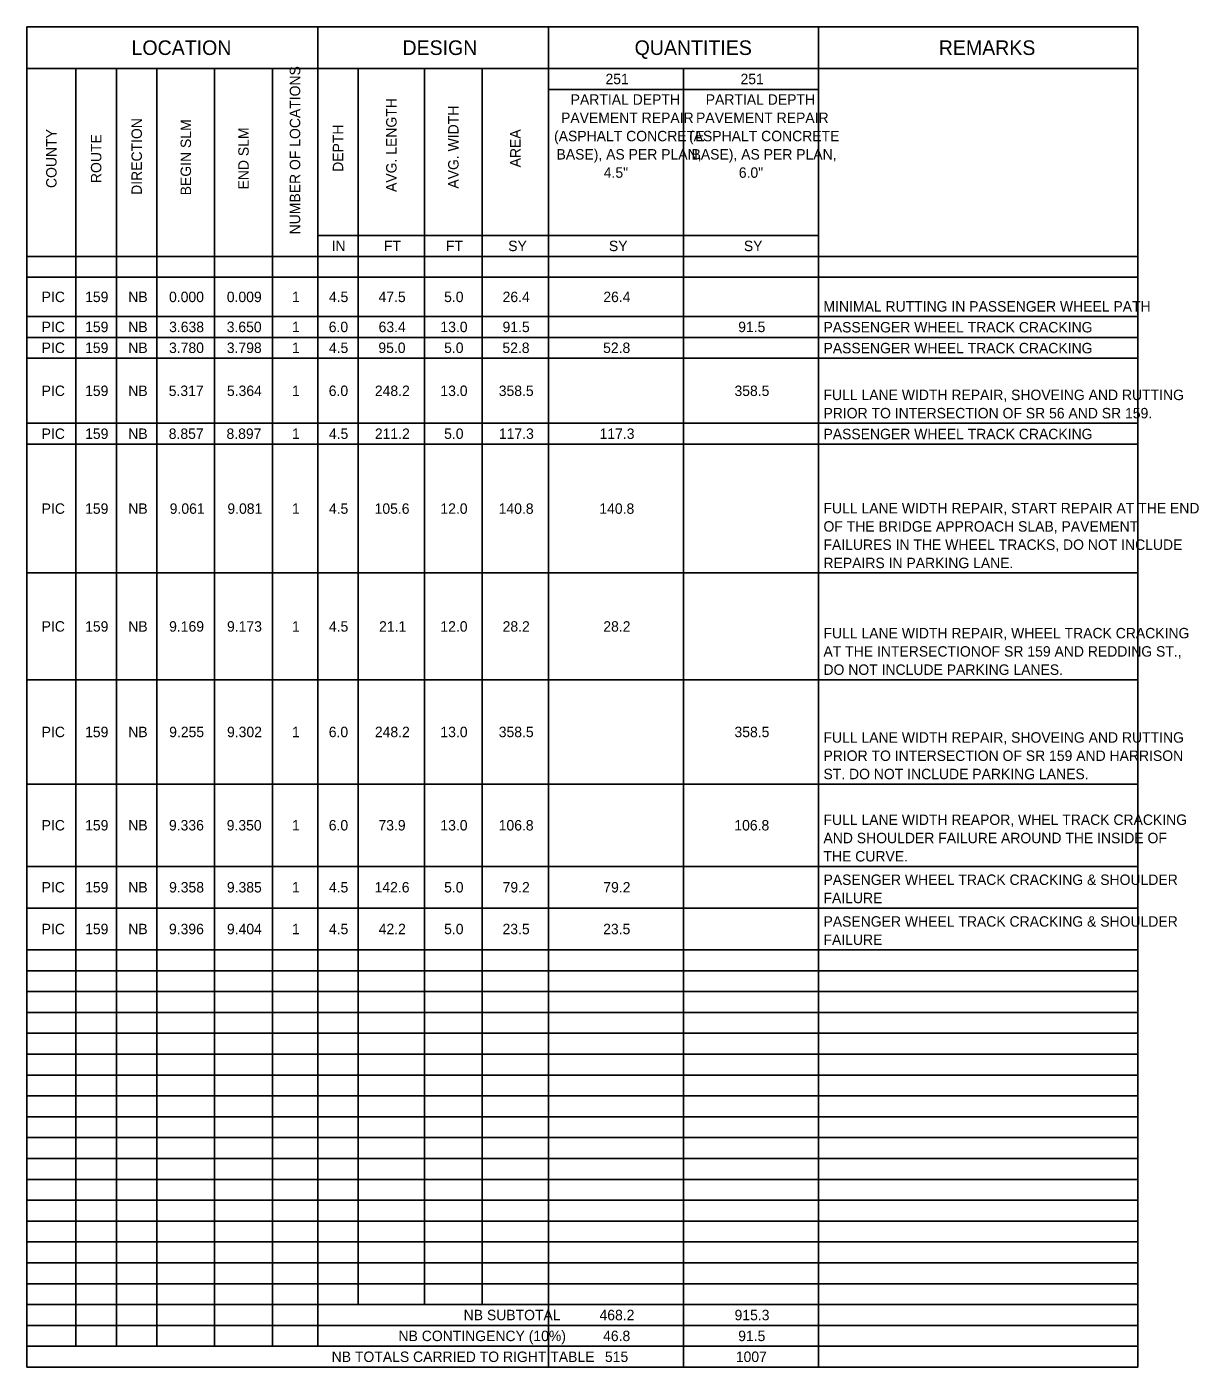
# Model space of a CAD drawing. Extents: x 0 to 66.4, y 0 to 22.
# Drawn here: x 35.12 to 50.75, y 3.76 to 21.75 of the extents above; entities that cross this region are included whole.
import ezdxf

# ---------------------------------------------------------------- set-up
doc = ezdxf.new("R2010")
doc.units = 0
doc.layers.add('Default', color=7, linetype='Continuous')

msp = doc.modelspace()

# ---------------------------------------------------------------- linework, layer by layer
at = {"layer": 'Default'}
for p, q in [((35.118, 21.75), (50.023, 21.75)), ((35.118, 21.75), (35.118, 3.764)), ((39.021, 21.75), (39.021, 4.044)), ((42.118, 21.75), (42.118, 3.764)), ((45.741, 21.75), (45.741, 3.764)), ((50.023, 21.75), (50.023, 3.764)), ((35.118, 21.19), (50.023, 21.19)), ((35.776, 21.19), (35.776, 4.044)), ((36.32, 21.19), (36.32, 4.044)), ((36.863, 21.19), (36.863, 4.044)), ((37.638, 21.19), (37.638, 4.044)), ((38.412, 21.19), (38.412, 4.044)), ((39.565, 21.19), (39.565, 4.604)), ((40.454, 21.19), (40.454, 4.604)), ((41.228, 21.19), (41.228, 4.604)), ((43.929, 21.19), (43.929, 3.764)), ((42.118, 20.91), (45.741, 20.91)), ((39.021, 18.95), (45.741, 18.95)), ((35.118, 18.67), (50.023, 18.67)), ((35.118, 18.39), (50.023, 18.39)), ((35.118, 17.863), (50.023, 17.863)), ((35.118, 17.583), (50.023, 17.583)), ((35.118, 17.303), (50.023, 17.303)), ((35.118, 16.43), (50.023, 16.43)), ((35.118, 16.15), (50.023, 16.15)), ((35.118, 14.421), (50.023, 14.421)), ((35.118, 12.988), (50.023, 12.988)), ((35.118, 11.588), (50.023, 11.588)), ((35.118, 10.484), (50.023, 10.484)), ((35.118, 9.924), (50.023, 9.924)), ((35.118, 9.364), (50.023, 9.364)), ((35.118, 9.084), (50.023, 9.084)), ((35.118, 8.804), (50.023, 8.804)), ((35.118, 8.524), (50.023, 8.524)), ((35.118, 8.244), (50.023, 8.244)), ((35.118, 7.964), (50.023, 7.964)), ((35.118, 7.684), (50.023, 7.684)), ((35.118, 7.404), (50.023, 7.404)), ((35.118, 7.124), (50.023, 7.124)), ((35.118, 6.844), (50.023, 6.844)), ((35.118, 6.564), (50.023, 6.564)), ((35.118, 6.284), (50.023, 6.284)), ((35.118, 6.004), (50.023, 6.004)), ((35.118, 5.724), (50.023, 5.724)), ((35.118, 5.444), (50.023, 5.444)), ((35.118, 5.164), (50.023, 5.164)), ((35.118, 4.884), (50.023, 4.884)), ((35.118, 4.604), (50.023, 4.604)), ((35.118, 4.324), (50.023, 4.324)), ((35.118, 4.044), (50.023, 4.044)), ((35.118, 3.764), (50.023, 3.764))]:
    msp.add_line(p, q, dxfattribs=at)

# ---------------------------------------------------------------- texts
for s, height, p in [('LOCATION', 0.196, (36.523, 21.372)), ('DESIGN', 0.196, (40.158, 21.372)), ('QUANTITIES', 0.196, (43.273, 21.372)), ('REMARKS', 0.196, (47.354, 21.372)), ('251', 0.14, (42.882, 20.98)), ('251', 0.14, (44.694, 20.98)), ('PARTIAL DEPTH ', 0.14, (42.415, 20.704)), ('PARTIAL DEPTH ', 0.14, (44.227, 20.704)), ('PAVEMENT REPAIR ', 0.14, (42.286, 20.459)), ('PAVEMENT REPAIR ', 0.14, (44.097, 20.459)), ('(ASPHALT CONCRETE ', 0.14, (42.192, 20.214)), ('(ASPHALT CONCRETE ', 0.14, (44.003, 20.214)), ('BASE), AS PER PLAN, ', 0.14, (42.225, 19.969)), ('BASE), AS PER PLAN, ', 0.14, (44.037, 19.969)), ('4.5"', 0.14, (42.859, 19.724)), ('6.0"', 0.14, (44.671, 19.724)), ('IN', 0.14, (39.207, 18.74)), ('FT', 0.14, (39.909, 18.74)), ('FT', 0.14, (40.741, 18.74)), ('SY', 0.14, (41.577, 18.74)), ('SY', 0.14, (42.928, 18.74)), ('SY', 0.14, (44.739, 18.74)), ('PIC', 0.14, (35.317, 18.056)), ('159', 0.14, (35.9, 18.056)), ('NB', 0.14, (36.479, 18.056)), ('0.000', 0.14, (37.026, 18.056)), ('0.009', 0.14, (37.801, 18.056)), ('1', 0.14, (38.676, 18.056)), ('4.5', 0.14, (39.171, 18.056)), ('47.5', 0.14, (39.837, 18.056)), ('5.0', 0.14, (40.717, 18.056)), ('26.4', 0.14, (41.502, 18.056)), ('26.4', 0.14, (42.853, 18.056)), ('MINIMAL RUTTING IN PASSENGER WHEEL PATH', 0.14, (45.807, 17.929)), ('PIC', 0.14, (35.317, 17.653)), ('159', 0.14, (35.9, 17.653)), ('NB', 0.14, (36.479, 17.653)), ('3.638', 0.14, (37.027, 17.653)), ('3.650', 0.14, (37.8, 17.653)), ('1', 0.14, (38.676, 17.653)), ('6.0', 0.14, (39.169, 17.653)), ('63.4', 0.14, (39.838, 17.653)), ('13.0', 0.14, (40.667, 17.653)), ('91.5', 0.14, (41.501, 17.653)), ('91.5', 0.14, (44.663, 17.653)), ('PASSENGER WHEEL TRACK CRACKING', 0.14, (45.807, 17.649)), ('PIC', 0.14, (35.317, 17.373)), ('159', 0.14, (35.9, 17.373)), ('NB', 0.14, (36.479, 17.373)), ('3.780', 0.14, (37.026, 17.373)), ('3.798', 0.14, (37.801, 17.373)), ('1', 0.14, (38.676, 17.373)), ('4.5', 0.14, (39.171, 17.373)), ('95.0', 0.14, (39.835, 17.373)), ('5.0', 0.14, (40.717, 17.373)), ('52.8', 0.14, (41.499, 17.373)), ('52.8', 0.14, (42.85, 17.373)), ('PASSENGER WHEEL TRACK CRACKING', 0.14, (45.807, 17.369)), ('PIC', 0.14, (35.317, 16.796)), ('159', 0.14, (35.9, 16.796)), ('NB', 0.14, (36.479, 16.796)), ('5.317', 0.14, (37.022, 16.796)), ('5.364', 0.14, (37.803, 16.796)), ('1', 0.14, (38.676, 16.796)), ('6.0', 0.14, (39.169, 16.796)), ('248.2', 0.14, (39.788, 16.796)), ('13.0', 0.14, (40.667, 16.796)), ('358.5', 0.14, (41.45, 16.796)), ('358.5', 0.14, (44.613, 16.796)), ('FULL LANE WIDTH REPAIR, SHOVEING AND RUTTING ', 0.14, (45.807, 16.741)), ('PRIOR TO INTERSECTION OF SR 56 AND SR 159.', 0.14, (45.807, 16.496)), ('PIC', 0.14, (35.317, 16.22)), ('159', 0.14, (35.9, 16.22)), ('NB', 0.14, (36.479, 16.22)), ('8.857', 0.14, (37.022, 16.22)), ('8.897', 0.14, (37.797, 16.22)), ('1', 0.14, (38.676, 16.22)), ('4.5', 0.14, (39.171, 16.22)), ('211.2', 0.14, (39.788, 16.22)), ('5.0', 0.14, (40.717, 16.22)), ('117.3', 0.14, (41.452, 16.22)), ('117.3', 0.14, (42.803, 16.22)), ('PASSENGER WHEEL TRACK CRACKING', 0.14, (45.807, 16.216)), ('PIC', 0.14, (35.317, 15.215)), ('159', 0.14, (35.9, 15.215)), ('NB', 0.14, (36.479, 15.215)), ('9.061', 0.14, (37.035, 15.215)), ('9.081', 0.14, (37.809, 15.215)), ('1', 0.14, (38.676, 15.215)), ('4.5', 0.14, (39.171, 15.215)), ('105.6', 0.14, (39.784, 15.215)), ('12.0', 0.14, (40.667, 15.215)), ('140.8', 0.14, (41.449, 15.215)), ('140.8', 0.14, (42.8, 15.215)), ('FULL LANE WIDTH REPAIR, START REPAIR AT THE END ', 0.14, (45.807, 15.221)), ('OF THE BRIDGE APPROACH SLAB, PAVEMENT ', 0.14, (45.807, 14.976)), ('FAILURES IN THE WHEEL TRACKS, DO NOT INCLUDE ', 0.14, (45.807, 14.731)), ('REPAIRS IN PARKING LANE.', 0.14, (45.807, 14.486)), ('PIC', 0.14, (35.317, 13.634)), ('159', 0.14, (35.9, 13.634)), ('NB', 0.14, (36.479, 13.634)), ('9.169', 0.14, (37.027, 13.634)), ('9.173', 0.14, (37.804, 13.634)), ('1', 0.14, (38.676, 13.634)), ('4.5', 0.14, (39.171, 13.634)), ('21.1', 0.14, (39.844, 13.634)), ('12.0', 0.14, (40.667, 13.634)), ('28.2', 0.14, (41.502, 13.634)), ('28.2', 0.14, (42.853, 13.634)), ('FULL LANE WIDTH REPAIR, WHEEL TRACK CRACKING ', 0.14, (45.807, 13.544)), ('AT THE INTERSECTIONOF SR 159 AND REDDING ST., ', 0.14, (45.807, 13.299)), ('DO NOT INCLUDE PARKING LANES.', 0.14, (45.807, 13.054)), ('PIC', 0.14, (35.317, 12.218)), ('159', 0.14, (35.9, 12.218)), ('NB', 0.14, (36.479, 12.218)), ('9.255', 0.14, (37.028, 12.218)), ('9.302', 0.14, (37.804, 12.218)), ('1', 0.14, (38.676, 12.218)), ('6.0', 0.14, (39.169, 12.218)), ('248.2', 0.14, (39.788, 12.218)), ('13.0', 0.14, (40.667, 12.218)), ('358.5', 0.14, (41.45, 12.218)), ('358.5', 0.14, (44.613, 12.218)), ('FULL LANE WIDTH REPAIR, SHOVEING AND RUTTING ', 0.14, (45.807, 12.144)), ('PRIOR TO INTERSECTION OF SR 159 AND HARRISON ', 0.14, (45.807, 11.899)), ('ST. DO NOT INCLUDE PARKING LANES.', 0.14, (45.807, 11.654)), ('FULL LANE WIDTH REAPOR, WHEL TRACK CRACKING ', 0.14, (45.807, 11.04)), ('PIC', 0.14, (35.317, 10.966)), ('159', 0.14, (35.9, 10.966)), ('NB', 0.14, (36.479, 10.966)), ('9.336', 0.14, (37.025, 10.966)), ('9.350', 0.14, (37.8, 10.966)), ('1', 0.14, (38.676, 10.966)), ('6.0', 0.14, (39.169, 10.966)), ('73.9', 0.14, (39.836, 10.966)), ('13.0', 0.14, (40.667, 10.966)), ('106.8', 0.14, (41.449, 10.966)), ('106.8', 0.14, (44.611, 10.966)), ('AND SHOULDER FAILURE AROUND THE INSIDE OF ', 0.14, (45.807, 10.795)), ('THE CURVE.', 0.14, (45.807, 10.55)), ('PIC', 0.14, (35.317, 10.134)), ('159', 0.14, (35.9, 10.134)), ('NB', 0.14, (36.479, 10.134)), ('9.358', 0.14, (37.027, 10.134)), ('9.385', 0.14, (37.802, 10.134)), ('1', 0.14, (38.676, 10.134)), ('4.5', 0.14, (39.171, 10.134)), ('142.6', 0.14, (39.784, 10.134)), ('5.0', 0.14, (40.717, 10.134)), ('79.2', 0.14, (41.502, 10.134)), ('79.2', 0.14, (42.853, 10.134)), ('PASENGER WHEEL TRACK CRACKING & SHOULDER ', 0.14, (45.807, 10.235)), ('FAILURE', 0.14, (45.807, 9.99)), ('PIC', 0.14, (35.317, 9.574)), ('159', 0.14, (35.9, 9.574)), ('NB', 0.14, (36.479, 9.574)), ('9.396', 0.14, (37.025, 9.574)), ('9.404', 0.14, (37.803, 9.574)), ('1', 0.14, (38.676, 9.574)), ('4.5', 0.14, (39.171, 9.574)), ('42.2', 0.14, (39.839, 9.574)), ('5.0', 0.14, (40.717, 9.574)), ('23.5', 0.14, (41.501, 9.574)), ('23.5', 0.14, (42.851, 9.574)), ('PASENGER WHEEL TRACK CRACKING & SHOULDER ', 0.14, (45.807, 9.675)), ('FAILURE', 0.14, (45.807, 9.43)), ('NB SUBTOTAL', 0.14, (40.979, 4.394)), ('468.2', 0.14, (42.802, 4.394)), ('915.3', 0.14, (44.614, 4.394)), ('NB CONTINGENCY (10%)', 0.14, (40.105, 4.114)), ('46.8', 0.14, (42.85, 4.114)), ('91.5', 0.14, (44.663, 4.114)), ('NB TOTALS CARRIED TO RIGHT TABLE', 0.14, (39.208, 3.834)), ('515', 0.14, (42.875, 3.834)), ('1007', 0.14, (44.631, 3.834))]:
    msp.add_text(s, height=height, dxfattribs=at).set_placement(p)
for s, p in [('NUMBER OF LOCATIONS', (38.786, 18.965)), ('AVG. LENGTH', (40.079, 19.534)), ('DIRECTION', (36.662, 19.495)), ('AVG. WIDTH', (40.911, 19.579)), ('COUNTY', (35.517, 19.587)), ('BEGIN SLM', (37.321, 19.489)), ('END SLM', (38.095, 19.567)), ('DEPTH', (39.363, 19.804)), ('AREA', (41.743, 19.864)), ('ROUTE', (36.118, 19.653))]:
    msp.add_text(s, height=0.14, rotation=90, dxfattribs=at).set_placement(p)

doc.saveas('drawing.dxf')
